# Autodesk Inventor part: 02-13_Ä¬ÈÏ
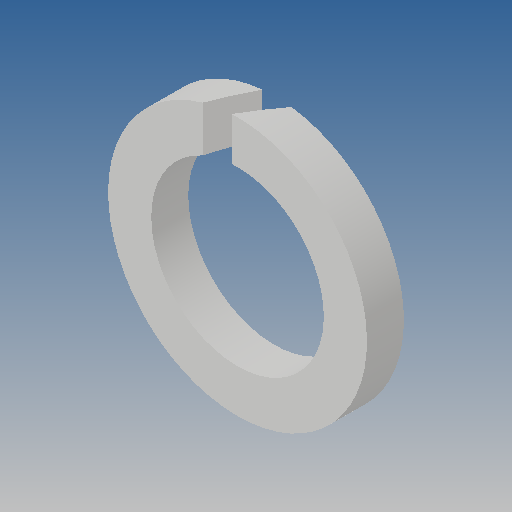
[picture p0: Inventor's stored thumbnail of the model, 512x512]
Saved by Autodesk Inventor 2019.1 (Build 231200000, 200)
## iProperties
Created: 2010-06
Part Number: 02-13_Ä¬ÈÏ
Material: Ogólny
Document SubType Name: Modeling
Designer: CADENGINEERING4
Density: 1 g/cm^3
Appearance: Domyślna
Author: CADENGINEERING4
Revision Number: ÈÎºÎ
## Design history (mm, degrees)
feature "NONE"
node "Bryła1"
